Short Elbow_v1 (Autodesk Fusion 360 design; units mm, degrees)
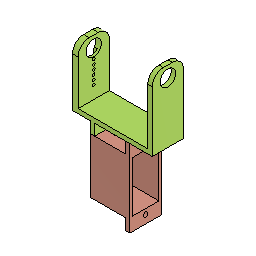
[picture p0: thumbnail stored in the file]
sketch "Sketch1" plane through (0, 0, 0) normal (0, 0, 1) x axis (1, 0, 0)
  line L1 (-17.85, -7) -> (17.85, -7)
  line L2 (-17.85, 7) -> (-17.85, -7)
  line L3 (17.85, 7) -> (-17.85, 7)
  line L4 (17.85, -7) -> (17.85, 7)
  line L5 (-17.85, 7) -> (17.85, -7)
  line L6 (17.85, 7) -> (-17.85, -7)
  line L7 (15.85, 7) -> (17.85, 7)
  line L8 (15.85, -7) -> (15.85, 7)
  line L9 (17.85, -7) -> (15.85, -7)
  line L10 (17.85, 7) -> (17.85, -7)
  line L11 (-15.35, 7) -> (-17.85, 7)
  line L12 (-15.35, -7) -> (-15.35, 7)
  line L13 (-17.85, -7) -> (-15.35, -7)
  line L14 (-17.85, 7) -> (-17.85, -7)
  point P6 (0, 0)
  point P1 (0, 0)
  point P4 (-17.85, 7)
  point P5 (17.85, 7)
  point P3 (-17.85, -7)
  point P7 (15.85, 7)
  point P10 (-15.35, 7)
  horizontal L1
  perpendicular L1 L2
  parallel L1 L3
  parallel L2 L4
  coincident L5 P6
  coincident L6 P6
  coincident P1 P6
  horizontal L7
  vertical L8
  horizontal L9
  vertical L10
  horizontal L11
  vertical L12
  horizontal L13
  vertical L14
  dimension "d1" distance P4 P5 = 35.7 (= "34 mm + 2 mm - 0.3 mm")
  dimension "d2" distance P3 P4 = 14
  dimension "d3" distance P5 P7 = 2
  dimension "d4" distance P4 P10 = 2.5
extrude "Extrude1" new body sketch "Sketch1" profile of L1 L3 L8 L12 along normal blind 2
extrude "Extrude2" add sketch "Sketch1" profile of L1 L3 L4 L7 L8 L9 L10 along normal blind 32 (= "2 mm + 30 mm")
sketch "Sketch2" plane through (17.85, 0, 0) normal (1, 0, 0) x axis (0, 1, 0)
  line L1 (7, 0) -> (-7, 0)
  line L2 (7, 32) -> (7, 0)
  line L3 (-7, 32) -> (7, 32)
  line L4 (-7, 0) -> (-7, 32)
  circle C1 centre (0, 27) radius 3.5
  point P6 (0, 27)
  dimension "d9" diameter C1 = 7
  dimension "d10" distance L3 P6 = 5 (= "( 7 / 2 ) * 1 mm + 1.5 mm")
extrude "Extrude3" cut sketch "Sketch2" profile of C1 against normal blind 2
extrude "Extrude4" add sketch "Sketch1" profile of L1 L2 L3 L11 L12 L13 L14 along normal blind 27 (= "2 mm + 25 mm")
fillet "Fillet1" radius 5
sketch "Sketch3" plane through (-17.85, 0, 0) normal (-1, 0, 0) x axis (0, -1, 0)
  line L1 (7, 0) -> (-7, 0)
  line L2 (7, 27) -> (7, 0)
  line L3 (-7, 27) -> (7, 27)
  line L4 (-7, 0) -> (-7, 27)
  line L5 (-1.997, 7.9409) -> (-2.65, 19.8909)
  line L6 (2.65, 19.8909) -> (1.997, 7.9409)
  line L7 (0, 27) -> (0, 0)
  line L8 (-7, 22.1) -> (7, 22.1)
  circle C1 centre (0, 13.65) radius 0.6
  circle C2 centre (0, 22.1) radius 2.3
  circle C3 centre (0, 9.65) radius 0.6
  arc A1 centre (0, 22.1) radius 3.45 clockwise from (-2.65, 19.8909) to (2.65, 19.8909)
  arc A2 centre (0, 8.05) radius 2 clockwise from (1.997, 7.9409) to (-1.997, 7.9409)
  circle C4 centre (0, 7.65) radius 0.6
  circle C5 centre (0, 11.65) radius 0.6
  circle C6 centre (0, 17.65) radius 0.6
  circle C7 centre (0, 15.65) radius 0.6
  circle C8 centre (0, 22.1) radius 3.45
  point P1 (0, 0)
  point P19 (0, 0)
  point P20 (0, 27)
  point P21 (7, 22.1)
  point P22 (-7, 22.1)
  coincident P1 P19
  midpoint L3 P20
  coincident L2 P21
  coincident L4 P22
  perpendicular L4 L8
  concentric C2 C8
  dimension "d19" distance L3 L8 = 4.9 (= "1.45 mm + ( 6.9 / 2 ) * 1 mm")
  dimension "d26" diameter C8 = 6.9
extrude "Extrude5" cut sketch "Sketch3" profile of L5 C1 L6 C3 A2 C4 C5 C6 C7 C8 against normal blind 1.4
extrude "Extrude8" cut sketch "Sketch3" profile of C1 C2 C3 A1 C4 C5 C6 C7 C8 against normal blind 2.5
fillet "Fillet2" radius 5
component_insert "Component Insert"
joint "Assemble" sketch "Sketch1" alignAngle 180 alignOffsetX 0 alignOffsetY -10 alignOffsetZ 0
sketch "Sketch5" plane through (0, 0, -5) normal (0, 0, 1) x axis (-1, 0, 0)
  line L1 (3.95, -2) -> (3.95, -1)
  line L2 (1.95, -2) -> (3.95, -2)
  line L3 (1.95, -1) -> (1.95, -2)
  line L4 (-5.85, -1) -> (1.95, -1)
  line L5 (-5.85, -7) -> (-5.85, -1)
  line L6 (9.95, -7) -> (-5.85, -7)
  line L7 (9.95, 7) -> (9.95, -7)
  line L8 (-5.85, 7) -> (9.95, 7)
  line L9 (-5.85, 1) -> (-5.85, 7)
  line L10 (1.95, 1) -> (-5.85, 1)
  line L11 (1.95, 2) -> (1.95, 1)
  line L12 (3.95, 2) -> (1.95, 2)
  line L13 (3.95, 1) -> (3.95, 2)
  line L14 (7.95, 1) -> (3.95, 1)
  line L15 (7.95, -1) -> (7.95, 1)
  line L16 (3.95, -1) -> (7.95, -1)
  line L17 (7.95, 7) -> (9.95, 7)
  line L18 (7.95, -7) -> (7.95, 7)
  line L19 (9.95, -7) -> (7.95, -7)
  line L20 (9.95, 7) -> (9.95, -7)
  point P9 (9.95, 7)
  point P18 (9.95, 7)
  point P19 (7.95, 7)
  point P21 (9.95, -7)
  horizontal L17
  vertical L18
  horizontal L19
  vertical L20
  coincident P9 P18
  dimension "d36" distance P18 P19 = 2
  dimension "d37" distance P18 P21 = 14
extrude "Extrude9" add sketch "Sketch5" profile of L6 L7 L8 L15 L17 L18 L19 L20 along normal blind 5
sketch "Sketch6" plane through (-9.95, 0, 0) normal (-1, 0, 0) x axis (0, -1, 0)
  line L1 (-7, -5) -> (7, -5)
  line L2 (-7, -29.7) -> (-7, -5)
  line L3 (7, -29.7) -> (-7, -29.7)
  line L4 (7, -5) -> (7, -29.7)
  circle C1 centre (0, -17.35) radius 3.5
  point P6 (0, -17.35)
  dimension "d40" diameter C1 = 7
  dimension "d41" distance L1 P6 = 12.35 (= "8.85 mm + ( 7 / 2 ) * 1 mm")
extrude "Extrude10" new body sketch "Sketch6" profile of C1 along normal blind 3
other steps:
joint_origin "JointOrigin2"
